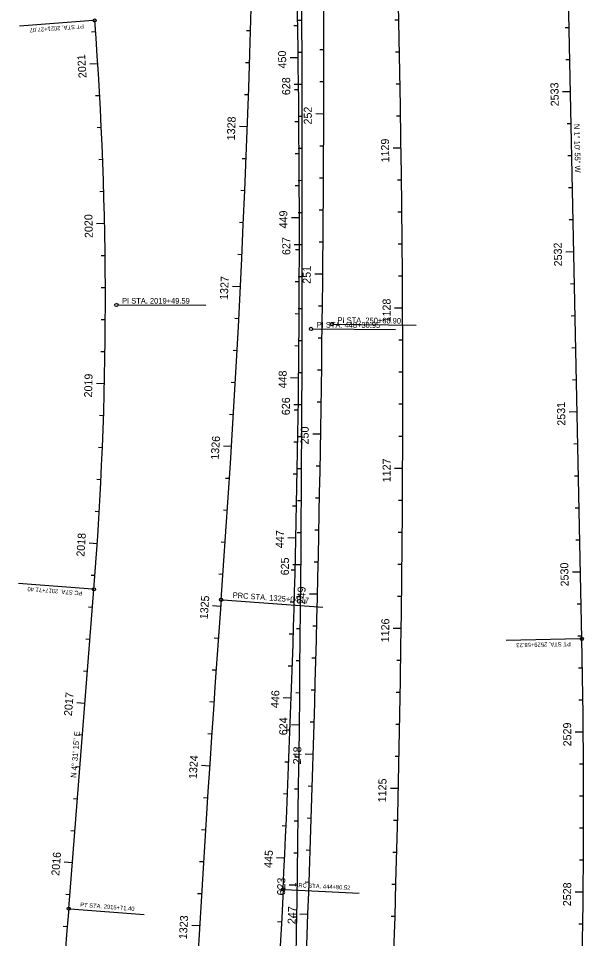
# Model space of a CAD drawing. Extents: x 919452 to 931278, y 583254 to 665650.
# Drawn here: x 928930 to 929283, y 638112 to 638687 of the extents above; entities that cross this region are included whole.
import ezdxf

# ---------------------------------------------------------------- set-up
doc = ezdxf.new("R2010")
doc.units = 0
for name, color, linetype in [('CLConst_dp', 7, 'Continuous'), ('CurveDataLabel_dp', 7, 'Continuous'), ('StationTicL_dp', 7, 'Continuous'), ('StationTicS_dp', 7, 'Continuous'), ('TextBLStation', 7, 'Continuous'), ('TextLabel', 7, 'Continuous')]:
    doc.layers.add(name, color=color, linetype=linetype)

msp = doc.modelspace()

# ---------------------------------------------------------------- linework, layer by layer
at = {"layer": 'CLConst_dp'}
for p, q in [((929281.82, 638299.08), (929270.93, 638827.01)), ((928961.45, 638130.65), (928977.22, 638330.03))]:
    msp.add_line(p, q, dxfattribs=at)
for centre, radius, start, end in [((920885.77, 638924.38), 8192.91, 355.794488, 5.343157), ((918208.05, 638452.43), 10962, 356.746791, 3.806041), ((914272.82, 638671.54), 14847.97, 357.696753, 0.946314), ((900459.43, 638571.38), 28647.89, 355.955427, 0.622371), ((920909.29, 638551), 8196.18, 357.14455, 2.041074), ((926692.52, 638510.68), 2291.83, 355.47906, 4.37084), ((942221.08, 637355.55), 13200, 175.794488, 180.562502), ((924158.91, 638193.39), 5124, 352.74679, 1.18191), ((942581.4, 637470.03), 13502.86, 177.14455, 179.560307), ((936146.52, 637562.53), 7207.49, 175.47906, 182.456288)]:
    msp.add_arc(centre, radius, start, end, dxfattribs=at)
at = {"layer": 'CurveDataLabel_dp'}
for p, q in [((928976.68, 638685.27), (928930.64, 638681.75)), ((928992.26, 638507.67), (929047.16, 638507.59)), ((929113.76, 638492.69), (929165.56, 638492.33)), ((929126.72, 638495.64), (929178.46, 638495.03)), ((928976.22, 638330.11), (928930.06, 638333.76)), ((929057.62, 638323.48), (929120.22, 638318.88)), ((929280.82, 638299.06), (929234.53, 638298.1)), ((929096.3, 638142.65), (929142.83, 638140.33)), ((928962.45, 638130.57), (929008.54, 638126.93))]:
    msp.add_line(p, q, dxfattribs=at)
for centre in [(928977.68, 638685.34), (928991.26, 638507.67), (929112.76, 638492.7), (929125.73, 638495.65), (928977.22, 638330.03), (929056.62, 638323.56), (929281.82, 638299.08), (929095.3, 638142.7), (928961.45, 638130.65)]:
    msp.add_circle(centre, 1, dxfattribs=at)
at = {"layer": 'StationTicL_dp'}
for p, q in [((929104.72, 638662.01), (929099.72, 638661.94)), ((928979.59, 638658.34), (928974.6, 638658.02)), ((929107.22, 638645.3), (929102.22, 638645.28)), ((929274.77, 638640.78), (929269.77, 638640.68)), ((929120.73, 638626.93), (929115.73, 638626.95)), ((929072.98, 638618.92), (929067.99, 638619.1)), ((929168.98, 638605.59), (929163.98, 638605.52)), ((929105.47, 638562.01), (929100.47, 638562.01)), ((928983.85, 638558.44), (928978.85, 638558.34)), ((929107.3, 638545.3), (929102.3, 638545.3)), ((929276.84, 638540.8), (929271.84, 638540.7)), ((929120.09, 638526.93), (929115.09, 638526.98)), ((929068.64, 638519.01), (929063.65, 638519.26)), ((929169.92, 638505.6), (929164.92, 638505.57)), ((928983.75, 638458.45), (928978.75, 638458.56)), ((929104.99, 638462.02), (929099.99, 638462.07)), ((929107.04, 638445.3), (929102.04, 638445.32)), ((929278.9, 638440.82), (929273.9, 638440.72)), ((929118.78, 638426.94), (929113.78, 638427.02)), ((929063.09, 638419.17), (929058.1, 638419.48)), ((929169.95, 638405.6), (929164.95, 638405.62)), ((929103.3, 638362.03), (929098.3, 638362.15)), ((928979.29, 638358.56), (928974.3, 638358.89)), ((929106.42, 638345.3), (929101.42, 638345.34)), ((929280.96, 638340.84), (929275.96, 638340.74)), ((929116.8, 638326.96), (929111.8, 638327.08)), ((929056.31, 638319.4), (929051.33, 638319.76)), ((929169.07, 638305.6), (929164.07, 638305.67)), ((928971.59, 638258.85), (928966.6, 638259.25)), ((929100.38, 638262.07), (929095.38, 638262.25)), ((929105.46, 638245.3), (929100.46, 638245.36)), ((929282.69, 638240.86), (929277.69, 638240.81)), ((929114.14, 638227), (929109.14, 638227.15)), ((929049.39, 638219.64), (929044.4, 638219.96)), ((929167.27, 638205.62), (929162.27, 638205.73)), ((928963.71, 638159.16), (928958.72, 638159.56)), ((929096.25, 638162.16), (929091.25, 638162.4)), ((929104.15, 638145.31), (929099.15, 638145.39)), ((929282.64, 638140.86), (929277.64, 638140.91)), ((929110.81, 638127.05), (929105.81, 638127.24)), ((929043.22, 638119.83), (929038.23, 638120.12))]:
    msp.add_line(p, q, dxfattribs=at)
at = {"layer": 'StationTicS_dp'}
for p, q in [((929107.09, 638685.3), (929104.59, 638685.29)), ((929167.57, 638685.58), (929165.07, 638685.53)), ((928978.21, 638678.29), (928975.72, 638678.11)), ((929075, 638678.88), (929072.5, 638678.96)), ((929104.43, 638682.01), (929101.93, 638681.97)), ((929273.95, 638680.77), (929271.45, 638680.72)), ((929107.16, 638665.3), (929104.66, 638665.29)), ((929120.79, 638666.93), (929118.29, 638666.93)), ((929167.98, 638665.58), (929165.48, 638665.54)), ((929274.36, 638660.78), (929271.86, 638660.72)), ((929074.38, 638658.89), (929071.88, 638658.97)), ((929104.97, 638642.01), (929102.47, 638641.98)), ((929120.77, 638646.93), (929118.27, 638646.94)), ((929168.35, 638645.59), (929165.85, 638645.54)), ((928980.79, 638638.38), (928978.29, 638638.24)), ((929073.7, 638638.9), (929071.21, 638638.99)), ((929107.27, 638625.3), (929104.77, 638625.29)), ((929168.68, 638625.59), (929166.18, 638625.55)), ((929105.17, 638622.01), (929102.67, 638621.99)), ((929275.19, 638620.78), (929272.69, 638620.73)), ((928981.81, 638618.4), (928979.32, 638618.29)), ((929105.32, 638602.01), (929102.82, 638602)), ((929107.3, 638605.3), (929104.8, 638605.29)), ((929120.65, 638606.93), (929118.15, 638606.94)), ((928982.67, 638598.42), (928980.17, 638598.33)), ((929072.21, 638598.93), (929069.71, 638599.03)), ((929275.6, 638600.79), (929273.1, 638600.74)), ((929107.31, 638585.3), (929104.81, 638585.29)), ((929120.55, 638586.93), (929118.05, 638586.95)), ((929169.24, 638585.59), (929166.74, 638585.56)), ((929071.39, 638578.95), (929068.9, 638579.05)), ((929105.42, 638582.01), (929102.92, 638582)), ((929276.01, 638580.79), (929273.51, 638580.74)), ((928983.35, 638578.43), (928980.85, 638578.36)), ((929107.32, 638565.3), (929104.82, 638565.3)), ((929120.43, 638566.93), (929117.93, 638566.95)), ((929169.47, 638565.6), (929166.97, 638565.57)), ((929070.53, 638558.97), (929068.03, 638559.08)), ((929276.42, 638560.8), (929273.92, 638560.75)), ((929120.27, 638546.93), (929117.77, 638546.95)), ((929169.65, 638545.6), (929167.15, 638545.58)), ((929069.61, 638538.99), (929067.11, 638539.11)), ((929105.47, 638542.01), (929102.97, 638542.02)), ((928984.18, 638538.44), (928981.68, 638538.41)), ((929105.42, 638522.01), (929102.92, 638522.02)), ((929107.28, 638525.3), (929104.78, 638525.3)), ((929169.81, 638525.6), (929167.31, 638525.58)), ((928984.33, 638518.44), (928981.83, 638518.43)), ((929277.25, 638520.81), (929274.75, 638520.75)), ((929107.24, 638505.3), (929104.74, 638505.3)), ((929119.88, 638506.93), (929117.38, 638506.96)), ((928984.31, 638498.44), (928981.81, 638498.46)), ((929067.63, 638499.04), (929065.13, 638499.17)), ((929105.33, 638502.01), (929102.83, 638502.03)), ((929277.66, 638500.81), (929275.16, 638500.76)), ((929119.65, 638486.94), (929117.15, 638486.97)), ((929105.19, 638482.01), (929102.69, 638482.04)), ((929107.19, 638485.3), (929104.69, 638485.3)), ((929170, 638485.6), (929167.5, 638485.59)), ((928984.12, 638478.44), (928981.62, 638478.48)), ((929066.57, 638479.07), (929064.07, 638479.2)), ((929278.07, 638480.81), (929275.57, 638480.76)), ((929107.12, 638465.3), (929104.62, 638465.31)), ((929119.38, 638466.94), (929116.88, 638466.97)), ((929170.04, 638465.6), (929167.54, 638465.59)), ((929065.46, 638459.1), (929062.96, 638459.24)), ((929278.49, 638460.82), (929275.99, 638460.77)), ((929119.1, 638446.94), (929116.6, 638446.98)), ((929104.75, 638442.02), (929102.25, 638442.05)), ((929170.05, 638445.6), (929167.55, 638445.6)), ((928983.21, 638438.46), (928980.71, 638438.53)), ((929064.3, 638439.13), (929061.8, 638439.28)), ((929106.94, 638425.3), (929104.44, 638425.31)), ((929170.02, 638425.6), (929167.52, 638425.6)), ((928982.49, 638418.47), (928979.99, 638418.57)), ((929104.46, 638422.02), (929101.96, 638422.06)), ((929279.31, 638420.83), (929276.81, 638420.78)), ((929118.44, 638406.95), (929115.94, 638406.99)), ((929104.12, 638402.02), (929101.62, 638402.07)), ((929106.83, 638405.3), (929104.33, 638405.31)), ((929279.72, 638400.83), (929277.22, 638400.78)), ((928981.6, 638398.49), (928979.1, 638398.61)), ((929061.83, 638399.21), (929059.33, 638399.37)), ((929106.71, 638385.3), (929104.21, 638385.31)), ((929118.07, 638386.95), (929115.57, 638387)), ((929169.85, 638385.6), (929167.35, 638385.61)), ((928980.53, 638378.52), (928978.04, 638378.66)), ((929060.52, 638379.25), (929058.03, 638379.42)), ((929103.73, 638382.03), (929101.23, 638382.08)), ((929280.14, 638380.84), (929277.64, 638380.78)), ((929117.67, 638366.95), (929115.17, 638367)), ((929106.57, 638365.3), (929104.07, 638365.32)), ((929169.71, 638365.6), (929167.21, 638365.62)), ((929280.55, 638360.84), (929278.05, 638360.79)), ((929059.17, 638359.3), (929056.67, 638359.47)), ((929117.25, 638346.96), (929114.75, 638347.01)), ((929169.53, 638345.6), (929167.03, 638345.62)), ((928977.88, 638338.61), (928975.39, 638338.79)), ((929057.76, 638339.34), (929055.27, 638339.52)), ((929102.81, 638342.04), (929100.31, 638342.1)), ((929102.28, 638322.04), (929099.78, 638322.11)), ((929106.26, 638325.3), (929103.76, 638325.32)), ((929169.32, 638325.6), (929166.82, 638325.63)), ((929281.37, 638320.85), (929278.87, 638320.8)), ((928976.32, 638318.67), (928973.83, 638318.86)), ((929106.08, 638305.3), (929103.58, 638305.32)), ((929116.32, 638306.97), (929113.82, 638307.03)), ((928974.74, 638298.73), (928972.25, 638298.93)), ((929054.87, 638299.45), (929052.37, 638299.63)), ((929101.69, 638302.05), (929099.2, 638302.13)), ((929281.79, 638300.85), (929279.29, 638300.8)), ((929115.81, 638286.97), (929113.31, 638287.04)), ((929101.06, 638282.06), (929098.56, 638282.14)), ((929105.89, 638285.3), (929103.39, 638285.33)), ((929168.78, 638285.6), (929166.28, 638285.64)), ((929282.17, 638280.86), (929279.67, 638280.81)), ((928973.16, 638278.79), (928970.67, 638278.99)), ((929053.45, 638279.5), (929050.96, 638279.67)), ((929105.68, 638265.3), (929103.18, 638265.33)), ((929115.28, 638266.98), (929112.78, 638267.05)), ((929168.46, 638265.61), (929165.96, 638265.65)), ((929052.07, 638259.55), (929049.57, 638259.72)), ((929282.47, 638260.86), (929279.97, 638260.83)), ((929114.72, 638246.99), (929112.22, 638247.06)), ((929168.1, 638245.61), (929165.6, 638245.66)), ((929050.71, 638239.59), (929048.22, 638239.76)), ((929099.65, 638242.09), (929097.15, 638242.18)), ((928970.01, 638238.92), (928967.52, 638239.11)), ((929105.23, 638225.3), (929102.73, 638225.33)), ((929167.7, 638225.61), (929165.2, 638225.67)), ((928968.44, 638218.98), (928965.94, 638219.17)), ((929098.87, 638222.1), (929096.38, 638222.2)), ((929282.84, 638220.86), (929280.34, 638220.85)), ((929104.98, 638205.31), (929102.48, 638205.34)), ((929113.53, 638207.01), (929111.03, 638207.09)), ((929048.1, 638199.68), (929045.6, 638199.84)), ((929098.05, 638202.12), (929095.55, 638202.23)), ((929282.91, 638200.86), (929280.41, 638200.86)), ((928966.86, 638199.04), (928964.37, 638199.24)), ((929097.17, 638182.14), (929094.67, 638182.25)), ((929104.71, 638185.31), (929102.21, 638185.34)), ((929112.89, 638187.02), (929110.39, 638187.1)), ((929166.8, 638185.62), (929164.3, 638185.68)), ((928965.28, 638179.1), (928962.79, 638179.3)), ((929046.83, 638179.72), (929044.34, 638179.88)), ((929282.9, 638180.86), (929280.4, 638180.87)), ((929104.44, 638165.31), (929101.94, 638165.35)), ((929112.22, 638167.03), (929109.72, 638167.11)), ((929166.3, 638165.63), (929163.8, 638165.7)), ((929045.6, 638159.76), (929043.1, 638159.91)), ((929282.81, 638160.86), (929280.31, 638160.88)), ((929095.27, 638142.18), (929092.78, 638142.31)), ((929111.53, 638147.04), (929109.03, 638147.13)), ((929165.76, 638145.64), (929163.26, 638145.71)), ((928962.13, 638139.23), (928959.64, 638139.42)), ((929044.39, 638139.79), (929041.9, 638139.94)), ((929103.84, 638125.31), (929101.34, 638125.35)), ((929165.18, 638125.65), (929162.68, 638125.72)), ((928960.56, 638119.29), (928958.07, 638119.48)), ((929094.29, 638122.21), (929091.8, 638122.33)), ((929282.4, 638120.86), (929279.9, 638120.9))]:
    msp.add_line(p, q, dxfattribs=at)

# ---------------------------------------------------------------- texts
at = {"layer": 'CurveDataLabel_dp'}
for s, height, rotation, p in [('PT STA. 2021+27.07', 2.625, 184.37084, (928970.84, 638683.06)), ('PI STA. 2019+49.59', 3.5, 359.92495, (928994.76, 638508.54)), ('PI STA. 250+68.90', 3.5, 359.32153, (929129.24, 638496.49)), ('PI STA. 448+30.95', 3.5, 359.59281, (929116.26, 638493.55)), ('PC STA. 2017+71.40', 2.625, 175.47906, (928970.1, 638328.84)), ('PRC STA. 1325+04.17', 3.5, 355.79449, (929063.73, 638324.79)), ('PT STA. 2529+58.23', 2.625, 181.18191, (929274.86, 638297.18)), ('PRC STA. 444+80.52', 2.625, 357.14455, (929102.38, 638144.1)), ('PT STA. 2015+71.40', 2.625, 355.47906, (928968.57, 638131.84))]:
    msp.add_text(s, height=height, rotation=rotation, dxfattribs=at).set_placement(p)
at = {"layer": 'TextBLStation'}
for s, rotation, p in [('450', 90.77603, (929097.31, 638655.39)), ('2021', 93.69411, (928972.64, 638649.49)), ('628', 90.14782, (929099.74, 638638.71)), ('2533', 91.18191, (929267.46, 638631.79)), ('252', 89.82785, (929113.21, 638620.37)), ('1328', 87.86331, (929065.16, 638610.39)), ('1129', 90.80058, (929161.6, 638596.71)), ('2020', 91.19411, (928976.53, 638549.52)), ('449', 90.07697, (929097.98, 638555.47)), ('627', 89.94782, (929099.8, 638538.83)), ('2532', 91.18191, (929269.52, 638531.82)), ('251', 89.44197, (929112.53, 638520.87)), ('1327', 87.16398, (929060.72, 638510.68)), ('1128', 90.2779, (929162.46, 638496.74)), ('2019', 88.69411, (928976.05, 638449.84)), ('448', 89.37792, (929097.42, 638455.53)), ('626', 89.74782, (929099.51, 638438.8)), ('2531', 91.18191, (929271.57, 638432.29)), ('250', 89.05609, (929111.17, 638420.54)), ('1326', 86.46464, (929055.06, 638410.87)), ('1127', 89.75523, (929162.41, 638396.91)), ('447', 88.67886, (929095.65, 638355.73)), ('2018', 86.19411, (928971.22, 638350.26)), ('625', 89.54782, (929098.87, 638338.79)), ('2530', 91.18191, (929273.64, 638331.92)), ('249', 88.6702, (929109.15, 638320.6)), ('1325', 85.8126, (929048.19, 638311.16)), ('1126', 89.23255, (929161.45, 638296.92)), ('2017', 85.47906, (928963.42, 638250.75)), ('446', 87.97981, (929092.66, 638255.81)), ('624', 89.34782, (929097.89, 638238.9)), ('2529', 90.53083, (929275.27, 638232.01)), ('248', 88.28432, (929106.44, 638220.65)), ('1324', 86.24666, (929041.33, 638211.42)), ('1125', 88.70987, (929159.57, 638196.98)), ('2016', 85.47906, (928955.54, 638151)), ('445', 87.28075, (929088.44, 638155.96)), ('623', 89.14782, (929096.55, 638138.83)), ('2528', 89.41265, (929275.05, 638132.12)), ('247', 87.89844, (929103.08, 638120.86)), ('1323', 86.68072, (929035.22, 638111.44))]:
    msp.add_text(s, height=5, rotation=rotation, dxfattribs=at).set_placement(p)
at = {"layer": 'TextLabel'}
for s, rotation, p in [('N 1%%d 10\' 55" W', 271.18191, (929276.94, 638620.71)), ('N 4%%d 31\' 15" E', 85.47906, (928966.15, 638212.22))]:
    msp.add_text(s, height=3.5, rotation=rotation, dxfattribs=at).set_placement(p)

doc.saveas('drawing.dxf')
